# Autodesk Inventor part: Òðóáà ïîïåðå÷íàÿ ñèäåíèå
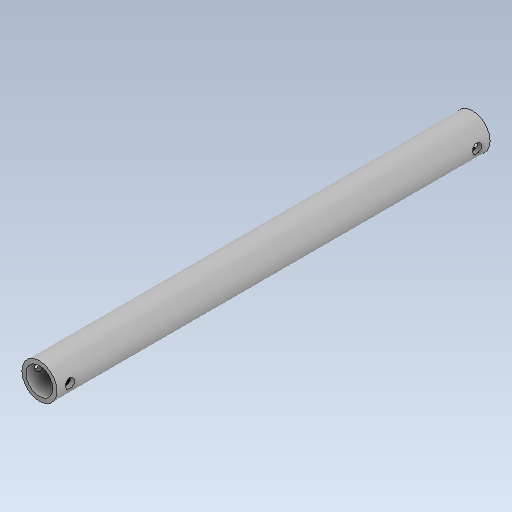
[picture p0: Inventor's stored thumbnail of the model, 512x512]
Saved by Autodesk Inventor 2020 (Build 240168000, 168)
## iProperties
Created: 1900-01
Part Number: Òðóáà ïîïåðå÷íàÿ ñèäåíèå
Material: Générique
Document SubType Name: Modeling
Designer: bruno
Density: 1 g/cm^3
Appearance: Par défaut
Author: bruno
Revision Number: ANYUNSPECIFIED
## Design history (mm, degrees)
feature "Base1"
node "Solide1"
